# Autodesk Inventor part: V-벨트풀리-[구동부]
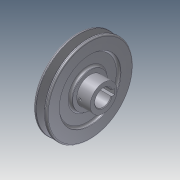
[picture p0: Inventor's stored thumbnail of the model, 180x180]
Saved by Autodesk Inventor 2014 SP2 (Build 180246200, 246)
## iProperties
Company: 한국ATC센터
Created: 2014-10
Part Number: V-벨트풀리-[구동부]
Document SubType Name: Modeling
Designer: 한국ATC센터
Density: 7.86 g/cm^3
Material: 강, 연강
Mass: 1515.01 g
Surface Area: 468.125 cm^2
Volume: 192.75 cm^3
Appearance: 강철
Author: KYOUNG IL JANG
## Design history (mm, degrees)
sketch "스케치1"
  geometry: L1 (-20, 0)-(20, 0); L2 (-20, 0)-(-20, 26); L3 (-20, 26)-(-16, 26); L4 (-16, 26)-(-16, 46); L5 (-16, 46)-(-20, 46); L6 (-20, 46)-(-20, 64.5); L7 (-20, 64.5)-(-16.062, 64.5); L8 (-16.062, 64.5)-(-12.001, 52); L9 (-12.001, 52)-(-7.999, 52); L10 (-7.999, 52)-(-3.938, 64.5); L11 (-3.938, 64.5)-(0, 64.5); L12 (0, 64.5)-(0, 46); L13 (0, 46)-(-4, 46); L14 (-4, 46)-(-4, 26); L15 (-4, 26)-(0, 26); L16 (0, 26)-(0, 20); L17 (0, 20)-(20, 20); L18 (20, 20)-(20, 0); L19 (-14.6, 60)-(-5.4, 60); 2 further points
  constraints: 38 end point, 11 parallel, 7 collinear, 3 equal length, 3 perpendicular, 2 point on line, 1 coincident, 1 horizontal, 1 midpoint
  dimensions: "d0" = 40 distance of L1.start L1.end; "d1" = 4.5 distance between parallel lines of L7 L19; "d2" = 8 distance between parallel lines of L9 L19; "d3" = 9.2 distance of L19.start L19.end; "d4" = 36 deg angle of L10 L8; "d5" = 20 distance between parallel lines of L12 L6; "d6" = 120 diameter of L19 L1; "d7" = 4 distance of L2.end L3.end; "d8" = 52 diameter of L3 L1; "d9" = 92 diameter of L5 L1; "d10" = 40 diameter of L17 L1
revolve "회전1" sketch "스케치1" stored, may be unused: angle "d11" = 90 deg
sketch "스케치2"
  geometry: L1 (-4, 11.843)-(-4, 16.5); L2 (-4, 16.5)-(4, 16.5); L3 (4, 16.5)-(4, 11.843); A1 r 12.5 centre (0, 0) between (-4, 11.843) and (4, 11.843); 1 further point
  constraints: 6 end point, 2 parallel, 2 point on circle, 1 centre point, 1 coincident, 1 horizontal, 1 vertical
  dimensions: "d12" = 25 diameter of A1; "d13" = 8 distance of L1.end L2.end; "d14" = 29 dimension on A1 L2
extrude "돌출1" cut sketch "스케치2" stored distance "d15" = 10; taper "d16" = 0 deg
chamfer "모따기1" distance "d17" = 1; stored, may be unused: second distance "d18" = 2, angle "d19" = 45 deg
node "작업 평면1"
sketch "스케치3"
  geometry: L1 (10, -20)-(10, 20) reference; 3 further points
  constraints: 1 horizontal alignment, 1 midpoint
  dimensions: "d20" = 15 distance from line of L1 point (-5, 0)
hole "구멍1" sketch "스케치3" at (-5, 0) diameter "d21" = 4.459; stored, may be unused: countersink angle "d25" = 90 deg, drill point angle "d27" = 118 deg; dims "d22" = 6, "d23" = 4, "d24" = 2, "d26" = 8
fillet "모깎기1" dims "d28" = 3, "d29" = 2, "d30" = 0.5, "d31" = 1
node "솔리드1"
